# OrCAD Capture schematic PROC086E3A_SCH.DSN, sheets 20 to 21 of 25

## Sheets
20 24. FPD LINK-III DESERIALIZER: size C; title: FPD LINK-III De-SERIALIZER
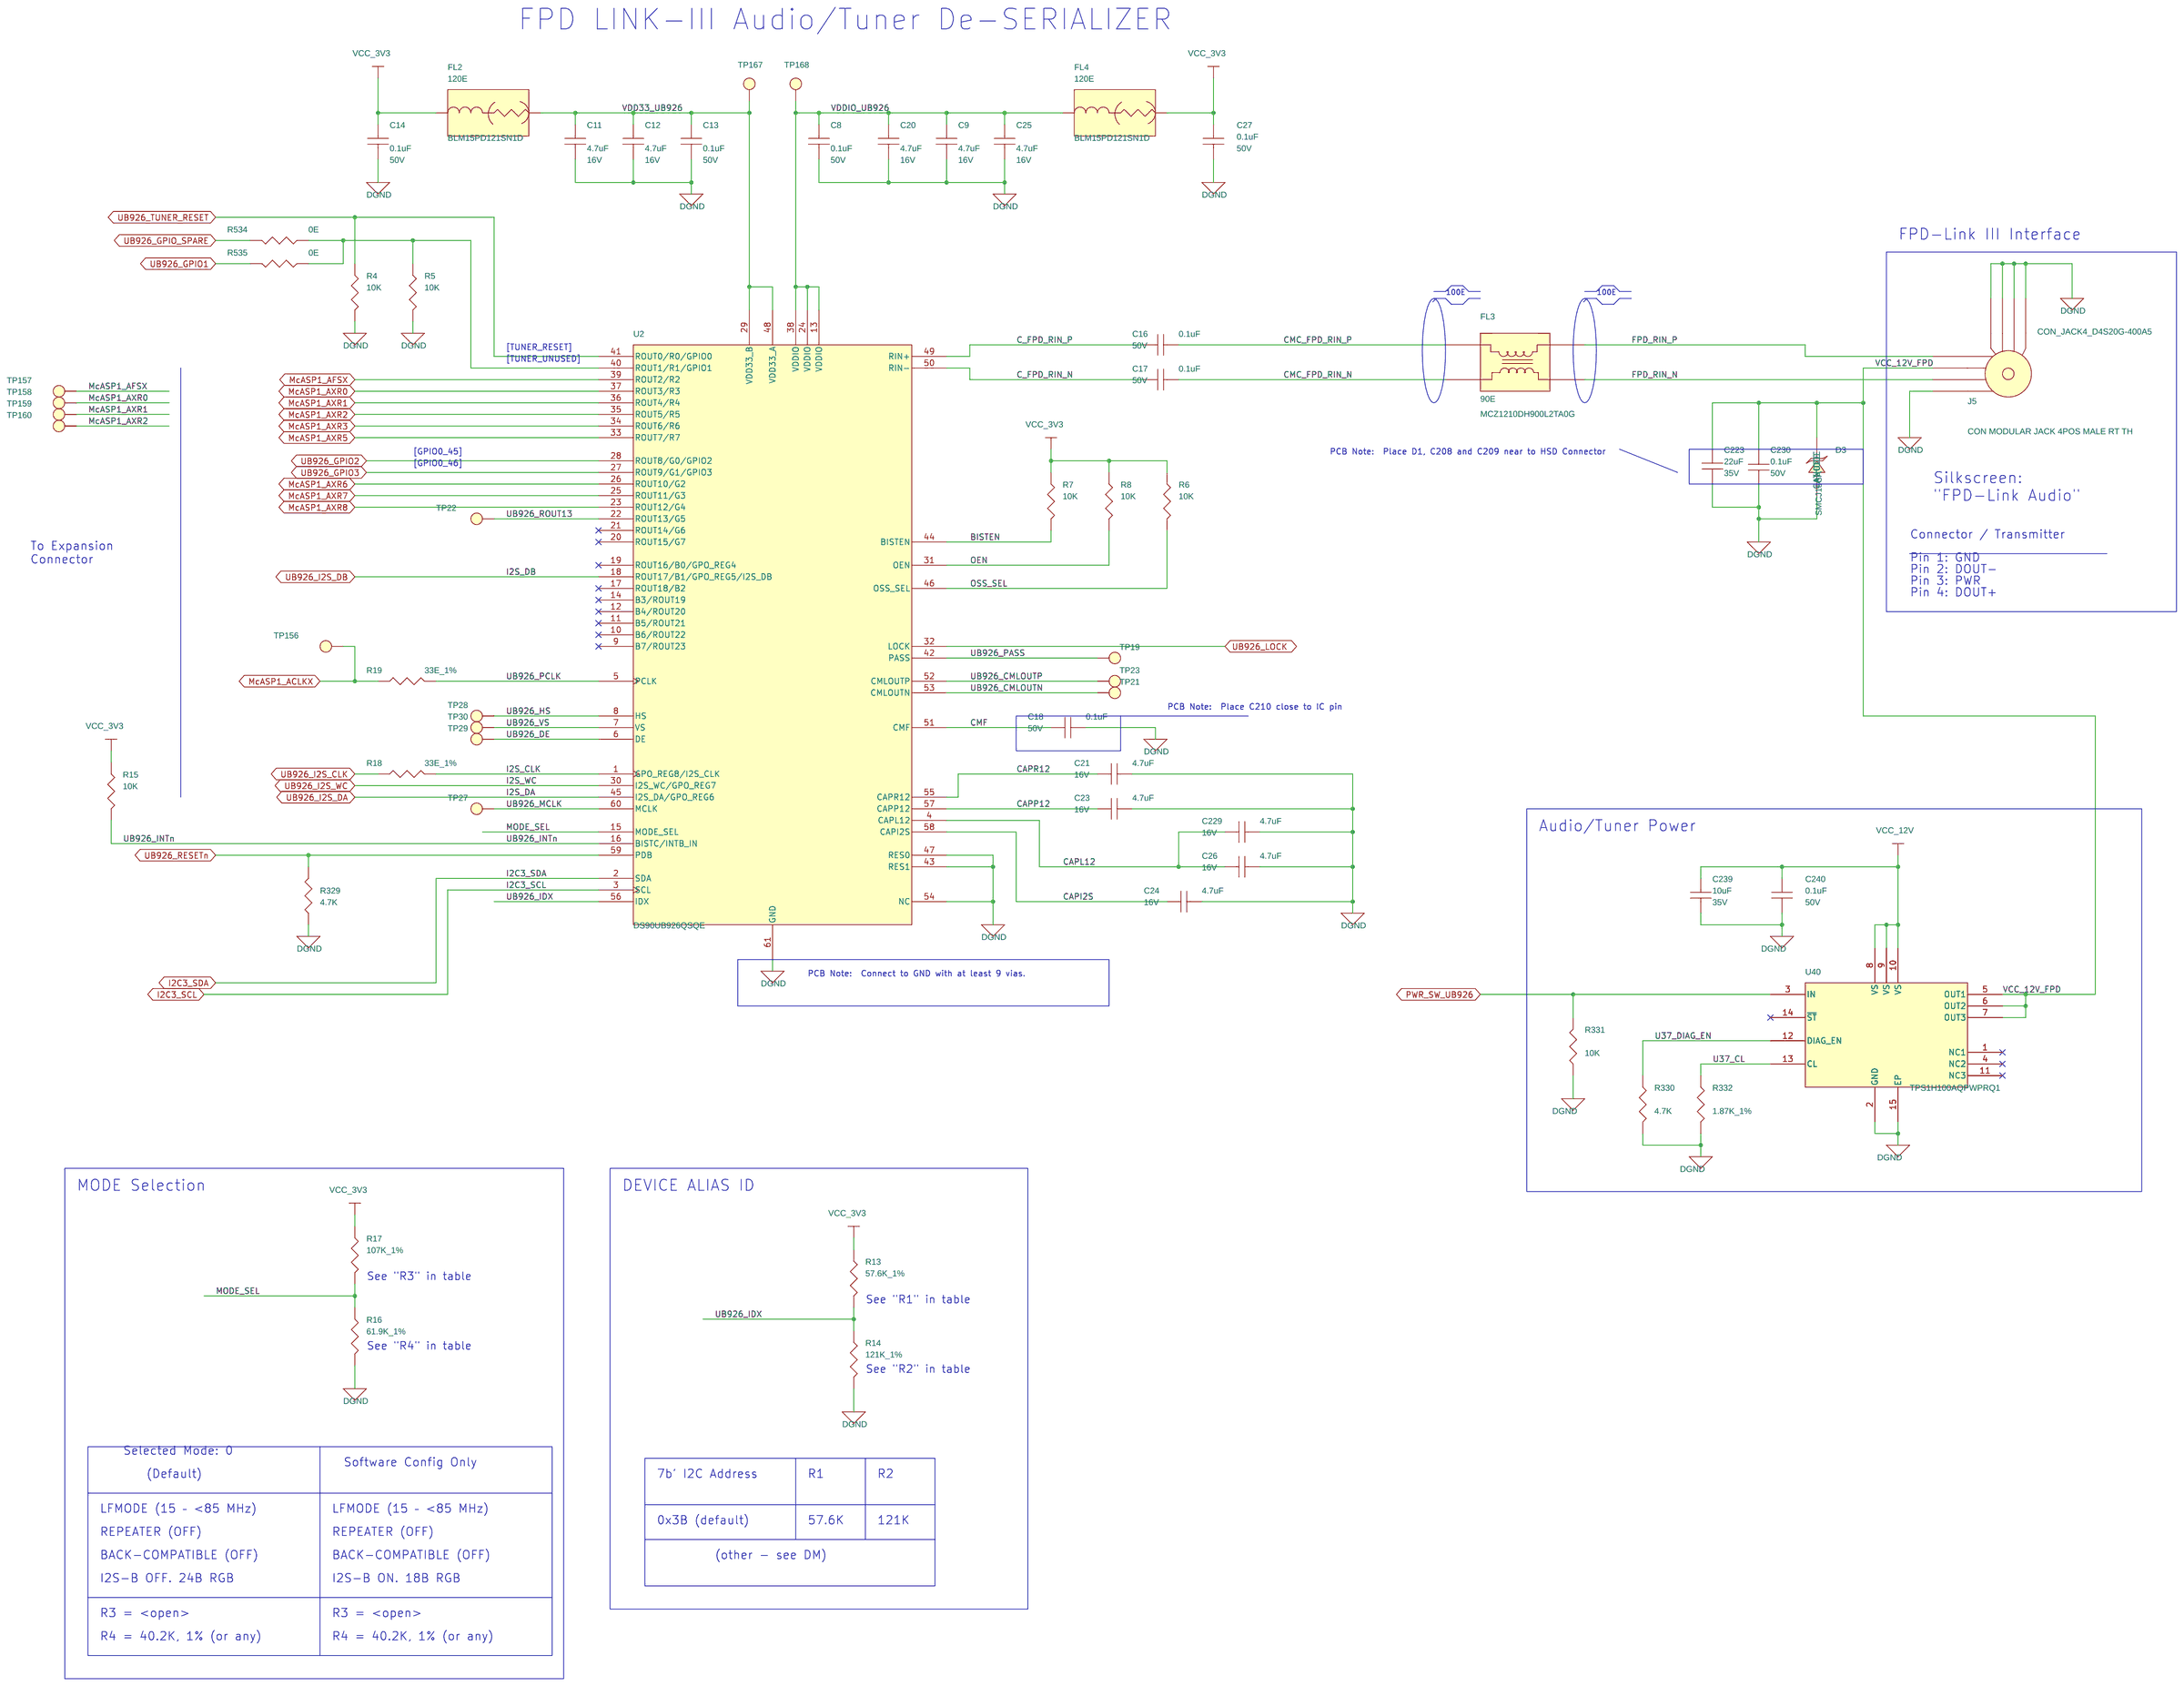
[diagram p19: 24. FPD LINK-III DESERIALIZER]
21 19. LI/OV CAM MUX: size C; title: LI/OV CAM MUX
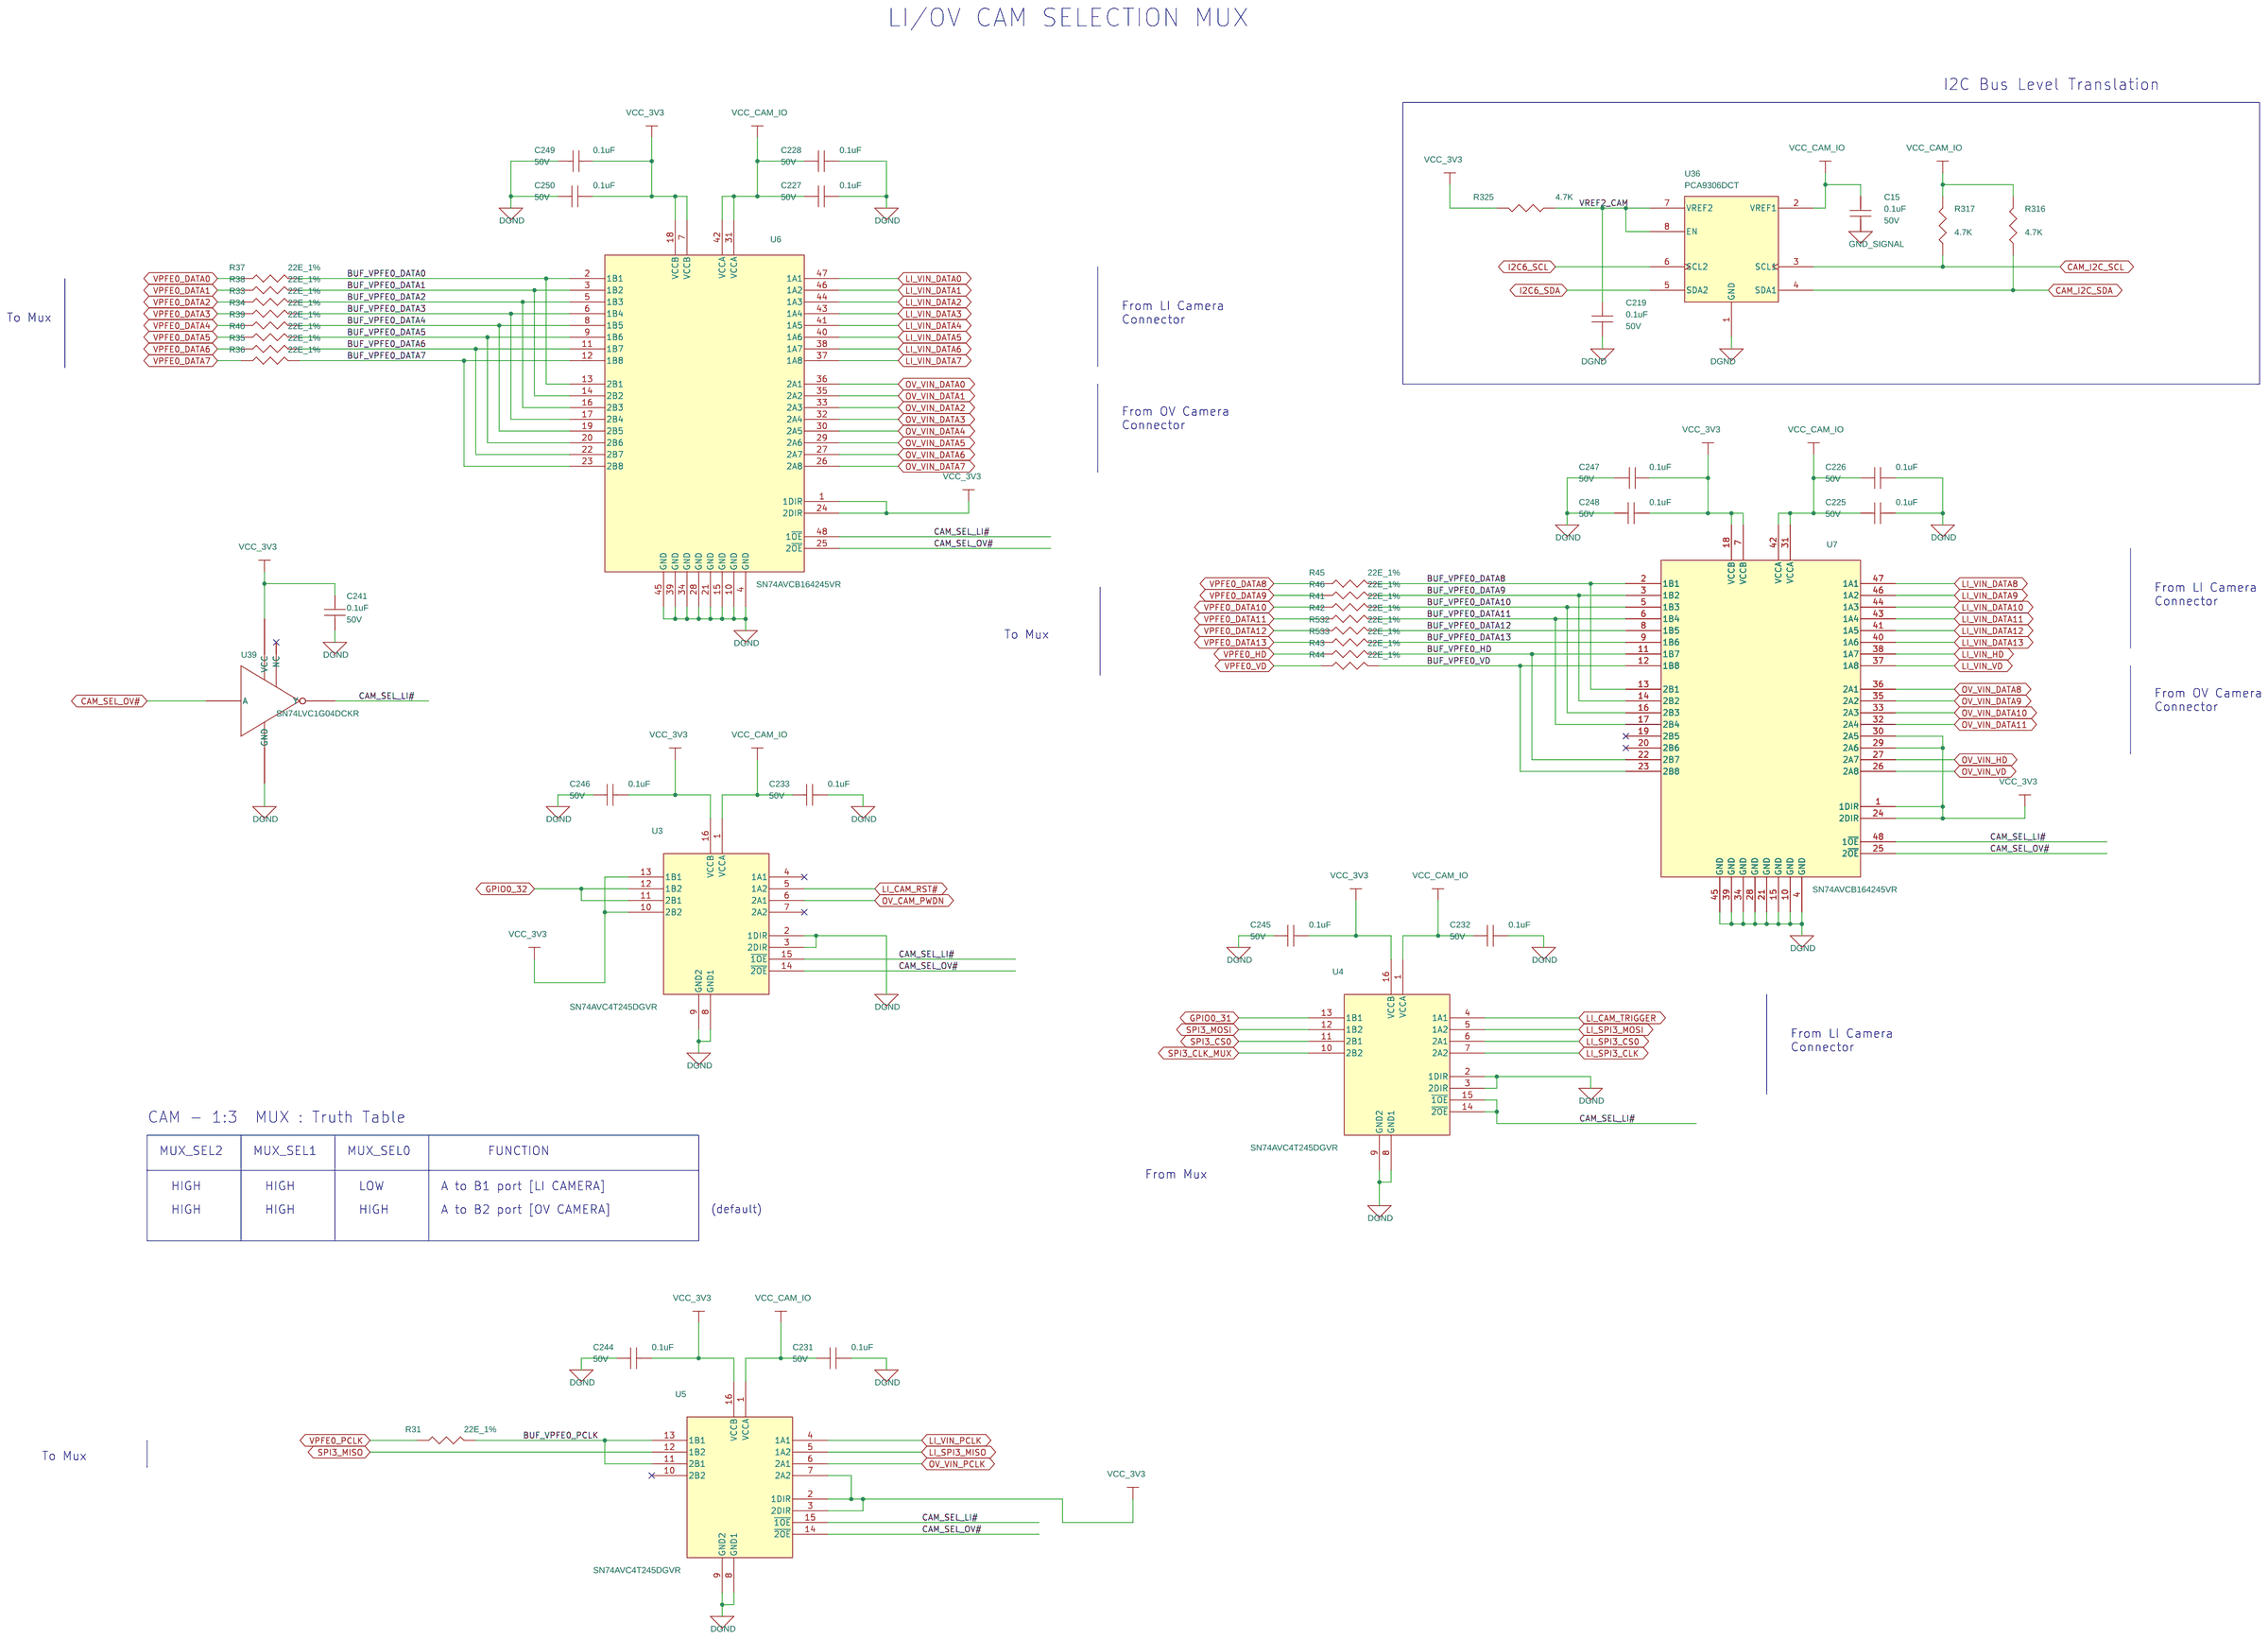
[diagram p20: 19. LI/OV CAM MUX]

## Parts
sheet 19. LI/OV CAM MUX
C15  0.1uF  [CAP0402_0-75]
C219  0.1uF  [CAP0402_0-75]
C225  0.1uF  [CAP0402_0-75]
C226  0.1uF  [CAP0402_0-75]
C227  0.1uF  [CAP0402_0-75]
C228  0.1uF  [CAP0402_0-75]
C231  0.1uF  [CAP0402_0-75]
C232  0.1uF  [CAP0402_0-75]
C233  0.1uF  [CAP0402_0-75]
C241  0.1uF  [CAP0402_0-75]
C244  0.1uF  [CAP0402_0-75]
C245  0.1uF  [CAP0402_0-75]
C246  0.1uF  [CAP0402_0-75]
C247  0.1uF  [CAP0402_0-75]
C248  0.1uF  [CAP0402_0-75]
C249  0.1uF  [CAP0402_0-75]
C250  0.1uF  [CAP0402_0-75]
R31  22E_1%  [RES0402_0-5]
R33  22E_1%  [RES0402_0-5]
R34  22E_1%  [RES0402_0-5]
R35  22E_1%  [RES0402_0-5]
R36  22E_1%  [RES0402_0-5]
R37  22E_1%  [RES0402_0-5]
R38  22E_1%  [RES0402_0-5]
R39  22E_1%  [RES0402_0-5]
R40  22E_1%  [RES0402_0-5]
R41  22E_1%  [RES0402_0-5]
R42  22E_1%  [RES0402_0-5]
R43  22E_1%  [RES0402_0-5]
R44  22E_1%  [RES0402_0-5]
R45  22E_1%  [RES0402_0-5]
R46  22E_1%  [RES0402_0-5]
R316  4.7K  [RES0402_0-5]
R317  4.7K  [RES0402_0-5]
R325  4.7K  [RES0402_0-5]
R532  22E_1%  [RES0402_0-5]
R533  22E_1%  [RES0402_0-5]
U3  SN74AVC4T245DGVR  [TVSOP16_15-74_150X180]
U4  SN74AVC4T245DGVR  [TVSOP16_15-74_150X180]
U5  SN74AVC4T245DGVR  [TVSOP16_15-74_150X180]
U6  SN74AVCB164245VR  [TVSOP48_15-74_390X180_1-2]
U7  SN74AVCB164245VR  [TVSOP48_15-74_390X180_1-2]
U36  PCA9306DCT  [SSOP8_25-59_120X110]
U39  SN74LVC1G04DCKR  [SC70-5]
sheet 24. FPD LINK-III DESERIALIZER
C8  0.1uF  [CAP0402_0-75]
C9  4.7uF  [CAP0603_1]
C11  4.7uF  [CAP0603_1]
C12  4.7uF  [CAP0603_1]
C13  0.1uF  [CAP0402_0-75]
C14  0.1uF  [CAP0402_0-75]
C16  0.1uF  [CAP0402_0-75]
C17  0.1uF  [CAP0402_0-75]
C18  0.1uF  [CAP0402_0-75]
C20  4.7uF  [CAP0603_1]
C21  4.7uF  [CAP0603_1]
C23  4.7uF  [CAP0603_1]
C24  4.7uF  [CAP0603_1]
C25  4.7uF  [CAP0603_1]
C26  4.7uF  [CAP0603_1]
C27  0.1uF  [CAP0402_0-75]
C223  22uF  [CAP1206_2]
C229  4.7uF  [CAP0603_1]
C230  0.1uF  [CAP0402_0-75]
C239  10uF  [CAP1206_2]
C240  0.1uF  [CAP0402_0-75]
D3  SMCJ15CA  [DIO_SMC]
FL2  120E  [EMIFIL_BLM15A_0402_0-6]
FL3  90E  [FILT4_MCZ1210DH_60X50_SMD_0-6]
FL4  120E  [EMIFIL_BLM15A_0402_0-6]
J5  CON_JACK4_D4S20G-400A5  [CON_JACK4_D4S20G-400A5_P_R_T_10-6]
R4  10K  [RES0402_0-5]
R5  10K  [RES0402_0-5]
R6  10K  [RES0402_0-5]
R7  10K  [RES0402_0-5]
R8  10K  [RES0402_0-5]
R13  57.6K_1%  [RES0402_0-5]
R14  121K_1%  [RES0402_0-5]
R15  10K  [RES0402_0-5]
R16  61.9K_1%  [RES0402_0-5]
R17  107K_1%  [RES0402_0-5]
R18  33E_1%  [RES0402_0-5]
R19  33E_1%  [RES0402_0-5]
R329  4.7K  [RES0402_0-5]
R330  4.7K  [RES0402_0-5]
R331  10K  [RES0402_0-5]
R332  1.87K_1%  [RES0402_0-5]
R534  0E  [RES0402_0-5]
R535  0E  [RES0402_0-5]
TP19  TP40_SMD  [TP40_SMD]
TP21  TP40_SMD  [TP40_SMD]
TP22  TP40_SMD  [TP40_SMD]
TP23  TP40_SMD  [TP40_SMD]
TP27  TP40_SMD  [TP40_SMD]
TP28  TP40_SMD  [TP40_SMD]
TP29  TP40_SMD  [TP40_SMD]
TP30  TP40_SMD  [TP40_SMD]
TP156  TP20_SMD  [TP20_SMD]
TP157  TP20_SMD  [TP20_SMD]
TP158  TP20_SMD  [TP20_SMD]
TP159  TP20_SMD  [TP20_SMD]
TP160  TP20_SMD  [TP20_SMD]
TP167  TP40_SMD  [TP40_SMD]
TP168  TP40_SMD  [TP40_SMD]
U2  DS90UB926QSQE  [WQFN60_19-68_360X360_0-8]
U40  TPS1H100AQPWPRQ1  [HTSSOP14_TPS1H100-Q1_180X200_1-2]

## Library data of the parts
C8 C13-C18 C27 C219 C225-C228 C230-C233 C240 C241 C244-C250 = CAP: CAP CERAMIC 0.1uF 50V 10% X7R 0402; Chkd/date: VASANTHA/281216; Crtd /date: CHAITHANYA/051011; Custom_Duty: 15%; Customs_HS_Code: 85322990; Distributor_name: DIGIKEY; Distributor_part_number: 445-173610-1-ND; Footprint Path: Y:\MIS_DATABASE\Library\ALTIUM_TOOL\PCB_FOOTPRINTS\Altium_Footprint_Lib.PcbLib; Height: 0.60MM; Library Path: Y:\MIS_DATABASE\Library\ALTIUM_TOOL\SCHEMATICS_PARTS\MS_DISCRETE_Library.schlib; Mfr_name: TDK CORPORATION; Mfr_part_number: C1005X7R1H104K050BE; Mistral Part No: 120011100014-R; Package: 0402; Part_type: CAPACITORS\CERAMIC; Project: VP-4000-BASE-BOARD; RoHS: RoHS; Temperature: -55°C+125°C; Tolerance: 10%; Voltage: 50V; Wattage: NA; Weight: 0.65mg; Datasheet: Y:\MIS_DATABASE\DATASHEETS\CAPACITORS\TDK_C-SER_FEB19.PDF
R31 R33-R46 R532 R533 = RESISTOR: RES 22E 1/16W 1% 0402; Chkd/date: SUHAS/290910; Crtd /date: MAZHAR/090909; Cust_part_number: 4700-80047E; Custom_Duty: 15%; Customs_HS_Code: 85332119; Distributor_name: DIGIKEY; Distributor_part_number: 311-22.0LRCT-ND; Footprint Path: Y:\MIS_DATABASE\Library\ALTIUM_TOOL\PCB_FOOTPRINTS\Altium_Footprint_Lib.PcbLib; Height: 0.40MM; Library Path: Y:\MIS_DATABASE\Library\ALTIUM_TOOL\SCHEMATICS_PARTS\MS_DISCRETE_Library.schlib; Mfr_name: YAGEO AMERICA; Mfr_part_number: RC0402FR-0722RL; Mistral Part No: 110009090004-R; Package: 0402; Part_type: RESISTORS\FIXED; Project: VMEFMCD; RoHS: RoHS; Temperature: -55°C+155°C; Tolerance: 1%; Voltage: NA; Wattage: 1/16W; Weight: 0.65mg; Datasheet: Y:\MIS_DATABASE\DATASHEETS\RESISTORS\RCXXXXL-SER_MAR18.PDF
R316 R317 R325 R329 R330 = RESISTOR: RES 4.7K 1/16W 5% 0402; Chkd/date: VASANTHA/281216; Crtd /date: BAVISH/010611; Custom_Duty: 15%; Customs_HS_Code: 85332119; Distributor_name: DIGIKEY; Distributor_part_number: 541-4.7KJCT-ND; Footprint Path: Y:\MIS_DATABASE\Library\ALTIUM_TOOL\PCB_FOOTPRINTS\Altium_Footprint_Lib.PcbLib; Height: 0.40MM; Library Path: Y:\MIS_DATABASE\Library\ALTIUM_TOOL\SCHEMATICS_PARTS\MS_DISCRETE_Library.schlib; Mfr_name: VISHAY; Mfr_part_number: CRCW04024K70JNED; Mistral Part No: 110011060001-R; Package: 0402; Part_type: RESISTORS\FIXED; Project: AM4515_EVM_LCD; RoHS: RoHS; Temperature: -55°C+155°C; Tolerance: 5%; Voltage: NA; Wattage: 1/16W; Weight: 0.65mg; Datasheet: Y:\MIS_DATABASE\DATASHEETS\RESISTORS\CRCW0603.PDF
U3-U5 = SN74AVC4T245DGVR_TVSOP16: IC 4-BIT DUAL SUPPLY BUS TRANSCEIVER TVSOP16; Chkd/date: SUHAS/251010; Crtd /date: MAZHAR/201109; Custom_Duty: 15%; Customs_HS_Code: 85423100; Distributor_name: DIGIKEY; Distributor_part_number: 296-18054-1-ND; Height: 1.20MM; Mfr_name: TEXAS INSTRUMENTS; Mistral Part No: 141009110005-P; Package: TVSOP16; Part_type: ICS\DIGITAL\COMBINATIONAL; Project: GOLDEN-I; RoHS: Sb/ Br FREE; Temperature: -40°C+85°C; Datasheet: Y:\MIS_DATABASE\DATASHEETS\ICS\DIGITAL\BUSTRANSCEIVER\SN74AVC4T245.PDF
U6 U7 = SN74AVCB164245VR_TVSOP48: IC 16-BIT DUAL-SUPPLY BUS TRANSCEIVER WITH 3-STATE O/Ps TVSOP48; Chkd/date: SUHAS/031110; Crtd /date: USMAN/300808; Custom_Duty: 15%; Customs_HS_Code: 85423100; Distributor_name: DIGIKEY; Distributor_part_number: 296-15550-1-ND; Footprint Path: Y:\MIS_DATABASE\Library\ALTIUM_TOOL\PCB_FOOTPRINTS\Altium_Footprint_Lib.PcbLib; Height: 1.20MM; Library Path: Y:\MIS_DATABASE\Library\ALTIUM_TOOL\SCHEMATICS_PARTS\MS_TELECOM_Library.schlib; Mfr_name: TEXAS INSTRUMENTS; Mistral Part No: 143009030062-R; Package: TVSOP48; Part_type: ICS\TELECOM\TRANSCEIVER; Project: MDC; Remarks: TBD Schematics symbol missing in database; RoHS: RoHS; Temperature: -40°C+85°C; Tolerance: NA; Voltage: NA; Wattage: NA; Weight: 123.5mg; Datasheet: Y:\MIS_DATABASE\DATASHEETS\ICS\DIGITAL\BUSTRANSCEIVER\SN74AVCB1642.PDF
U36 = PCA9306DCT_SSOP8: IC VOLTAGE LEVEL TRANSLATORS SSOP8; Chkd/date: MAZHAR/231210; Crtd /date: BAVISH/221210; Custom_Duty: 15%; Customs_HS_Code: 85423100; Distributor_name: DIGIKEY; Distributor_part_number: 296-18509-1-ND; Height: 1.30MM; Mfr_name: TEXAS INSTRUMENTS; Mfr_part_number: PCA9306DCTR; Mistral Part No: 141010120015-R; Package: SSOP8; Part_type: ICS\INTERFACE; Project: CENTAURUS; RoHS: RoHS; Temperature: -40°C+85°C; Tolerance: NA; Voltage: NA; Wattage: NA; Weight: NA; Datasheet: Y:\MIS_DATABASE\DATASHEETS\ICS\INTERFACE\PCA9306DCT.PDF
U39 = SN74LVC1G04DCKR_SC70-5: IC SINGLE INVERTER GATE SC70-5; Chkd/date: SUHAS/221010; Crtd /date: USMAN/150709; Custom_Duty: 15%; Customs_HS_Code: 85423100; Distributor_name: DIGIKEY; Distributor_part_number: 296-11600-1-ND; Height: 1.10MM; Mfr_name: TEXAS INSTRUMENTS; Mistral Part No: 141009070007-R; Part_type: ICS\DIGITAL\GATES; Project: BUG_BASE-II; RoHS: Sb/ Br FREE; Temperature: -40°C+85°C; Datasheet: Y:\MIS_DATABASE\DATASHEETS\ICS\DIGITAL\GATES\SN74LVC1G04-1.PDF
C9 C11 C12 C20 C21 C23-C26 C229 = CAP: CAP CERAMIC 4.7uF 16V 10% X6S 0603; Chkd/date: MANIRAJA/050618; Crtd /date: ALVY/050618; Custom_Duty: 15%; Customs_HS_Code: 85322990; Distributor_name: DIGIKEY; Distributor_part_number: 445-9118-1-ND; Footprint Path: Y:\MIS_DATABASE\Library\ALTIUM_TOOL\PCB_FOOTPRINTS\Altium_Footprint_Lib.PcbLib; Height: 1.00MM; Library Path: Y:\MIS_DATABASE\Library\ALTIUM_TOOL\SCHEMATICS_PARTS\MS_DISCRETE_Library.schlib; Mfr_name: TDK CORPORATION; Mfr_part_number: C1608X6S1C475K080AC; Mistral Part No: 120018060012-R; Package: 0603; Part_type: CAPACITORS\CERAMIC; Project: NPOL_RDAQ_ONBOARD-RX; RoHS: RoHS; Temperature: -55°C+105°C; Tolerance: 10%; Voltage: 16V; Wattage: NA; Weight: 2mg; Datasheet: Y:\MIS_DATABASE\DATASHEETS\CAPACITORS\TDK_C-SER-JUL17.PDF
C223 = CAP: CAP CERAMIC 22uF 35V 20% X5R 1206; Chkd/date: MANIRAJA/130318; Crtd /date: MANIRAJA/130318; Custom_Duty: 15%; Customs_HS_Code: 85322990; Distributor_name: DIGIKEY; Distributor_part_number: 445-8045-1-ND; Footprint Path: Y:\MIS_DATABASE\Library\ALTIUM_TOOL\PCB_FOOTPRINTS\Altium_Footprint_Lib.PcbLib; Height: 1.80MM; Library Path: Y:\MIS_DATABASE\Library\ALTIUM_TOOL\SCHEMATICS_PARTS\MS_DISCRETE_Library.schlib; Mfr_name: TDK CORPORATION; Mfr_part_number: C3216X5R1V226M160AC; Mistral Part No: 120018030003-R; Package: 1206; Part_type: CAPACITORS\CERAMIC; Project: TI_SVB_MAXWELL_VPS; RoHS: RoHS; Temperature: -55°C+85°C; Tolerance: 20%; Voltage: 35V; Wattage: NA; Weight: 16.2mg; Datasheet: Y:\MIS_DATABASE\DATASHEETS\CAPACITORS\C3216X5R1V226M160AC.PDF
C239 = CAP: CAP CERAMIC 10uF 35V 10% X5R 1206; Chkd/date: MANIRAJA/160519; Crtd /date: ALVY/160519; Custom_Duty: 15%; Customs_HS_Code: 85322990; Distributor_name: DIGIKEY; Distributor_part_number: 587-2484-1-ND; Footprint Path: Y:\MIS_DATABASE\Library\ALTIUM_TOOL\PCB_FOOTPRINTS\Altium_Footprint_Lib.PcbLib; Height: 1.80MM; Library Path: Y:\MIS_DATABASE\Library\ALTIUM_TOOL\SCHEMATICS_PARTS\MS_DISCRETE_Library.schlib; Mfr_name: TAIYO YUDEN; Mfr_part_number: GMK316BJ106KL-T; Mistral Part No: 120019050012-R; Package: 1206; Part_type: CAPACITORS\CERAMIC; Project: J7ES_SOM_DUAL-LEO_PMIC; RoHS: RoHS; Temperature: -55°C+85°C; Tolerance: 10%; Voltage: 35V; Wattage: NA; Weight: 16.2mg; Datasheet: Y:\MIS_DATABASE\DATASHEETS\CAPACITORS\TY-EMKXXX-2019.PDF
D3 = DIODE_TVS: DIODE TVS 1500W 15V SMC; Chkd/date: SUHAS/061010; Crtd /date: MAZHAR/011007; Custom_Duty: 15%; Customs_HS_Code: 85412900; Distributor_name: DIGIKEY; Distributor_part_number: SMCJ15CALFCT-ND; Height: 2.62MM; Mfr_name: LITTLE FUSE; Mistral Part No: 130009030286-R; Package: SMC; Part_type: DIODE\TVS; Project: TELEMETRY ENCODER; RoHS: RoHS; Temperature: -55°C+150°C; Voltage: 15V; Wattage: 1500W; Weight: 0.21g; Datasheet: Y:\MIS_DATABASE\DATASHEETS\DISCRETES\DIODES\SMCJ-LITT.PDF
FL2 FL4 = EMIFILTER_IND: IND FERRITE BEAD CHIP 120E 1.3A 0402; Chkd/date: VASANTHA/010117; Crtd /date: CHAITHANYA/150312; Custom_Duty: 24%; Customs_HS_Code: 85437099; Distributor_name: DIGIKEY; Distributor_part_number: 490-5203-1-ND; Footprint Path: Y:\MIS_DATABASE\Library\ALTIUM_TOOL\PCB_FOOTPRINTS\Altium_Footprint_Lib.PcbLib; Height: 0.55MM; Library Path: Y:\MIS_DATABASE\Library\ALTIUM_TOOL\SCHEMATICS_PARTS\MS_FILTER_Library.schlib; Mfr_name: MURATA; Mfr_part_number: BLM15PD121SN1D; Mistral Part No: 130012030043-R; Package: 0402; Part_type: FILTER; Project: GEN_3-8; RoHS: RoHS; Temperature: -55°C+125°C; Tolerance: 25%; Voltage: NA; Wattage: NA; Weight: 0.65mg; Datasheet: Y:\MIS_DATABASE\DATASHEETS\DISCRETES\INDUCTORS\BLM15X-SER.PDF
FL3 = EMIFILTER_ACM: FILTER COMMON MODE 90E 100mA SMD; Chkd/date: MANIRAJA/220818; Crtd /date: ALVY/220818; Custom_Duty: 24%; Customs_HS_Code: 85437099; Distributor_name: DIGIKEY; Distributor_part_number: 445-174550-1-ND; Footprint Path: Y:\MIS_DATABASE\Library\ALTIUM_TOOL\PCB_FOOTPRINTS\Altium_Footprint_Lib.PcbLib; Height: 0.60MM; Library Path: Y:\MIS_DATABASE\Library\ALTIUM_TOOL\SCHEMATICS_PARTS\MS_FILTER_Library.schlib; Mfr_name: TDK CORPORATION; Mfr_part_number: MCZ1210DH900L2TA0G; Mistral Part No: 130018080027-R; Package: SMD; Part_type: FILTER; Project: TI_J7ES_EVM_FUSION2_SER_CAP; RoHS: RoHS; Temperature: -40°C+85°C; Tolerance: 25%; Voltage: NA; Wattage: NA; Weight: 3mg; Datasheet: Y:\MIS_DATABASE\DATASHEETS\ICS\MISC\MCZ1210DH-SER.PDF
J5 = CON_JACK4_EXG.0B.304: CON MODULAR JACK 4POS MALE RT TH; Chkd/date: MANIRAJA/031018; Crtd /date: ALVY/070818; Custom_Duty: 24%; Customs_HS_Code: 85369090; Distributor_name: DIGIKEY; Distributor_part_number: 1868-1516-1-ND; Footprint Path: Y:\MIS_DATABASE\Library\ALTIUM_TOOL\PCB_FOOTPRINTS\Altium_Footprint_Lib.PcbLib; Height: 10.60MM; Library Path: Y:\MIS_DATABASE\Library\ALTIUM_TOOL\SCHEMATICS_PARTS\MS_CONNECTOR_Library.schlib; Mfr_name: ROSENBERGER; Mfr_part_number: D4S20G-400A5-C; Mistral Part No: 150018080004-R; Package: THRU-HOLE; Part_type: CONNECTOR\JACK; Project: TI_J7ES_EVM_IB; RoHS: RoHS; Temperature: -40°C+105°C; Tolerance: NA; Voltage: NA; Wattage: NA; Weight: 8.6g; Datasheet: Y:\MIS_DATABASE\DATASHEETS\CONNECTORS\D4S20G-400A5-Y.PDF
R4-R6 R8 R15 R331 = RESISTOR: RES 10K 1/16W 5% 0402; Chkd/date: VASANTHA/061216; Crtd /date: MAZHAR/230805; Custom_Duty: 15%; Customs_HS_Code: 85332119; Distributor_name: DIGIKEY; Distributor_part_number: 311-10KJRCT-ND; Footprint Path: Y:\MIS_DATABASE\Library\ALTIUM_TOOL\PCB_FOOTPRINTS\Altium_Footprint_Lib.PcbLib; Height: 0.40MM; Library Path: Y:\MIS_DATABASE\Library\ALTIUM_TOOL\SCHEMATICS_PARTS\MS_DISCRETE_Library.schlib; Mfr_name: YAGEO AMERICA; Mfr_part_number: RC0402JR-0710KL; Mistral Part No: 110011060021-R; Package: 0402; Part_type: RESISTORS\FIXED; Project: HSE; RoHS: RoHS; Temperature: -55°C+155°C; Tolerance: 5%; Voltage: NA; Wattage: 1/16W; Weight: 0.65mg; Datasheet: Y:\MIS_DATABASE\DATASHEETS\RESISTORS\RCXXXXL-SER_MAR18.PDF
R7 = RESISTOR: RES 10K 1/16W 5% 0402; Assembly_Instruction: DNI; Chkd/date: VASANTHA/061216; Crtd /date: MAZHAR/230805; Custom_Duty: 15%; Customs_HS_Code: 85332119; Distributor_name: DIGIKEY; Distributor_part_number: 311-10KJRCT-ND; Footprint Path: Y:\MIS_DATABASE\Library\ALTIUM_TOOL\PCB_FOOTPRINTS\Altium_Footprint_Lib.PcbLib; Height: 0.40MM; Library Path: Y:\MIS_DATABASE\Library\ALTIUM_TOOL\SCHEMATICS_PARTS\MS_DISCRETE_Library.schlib; Mfr_name: YAGEO AMERICA; Mfr_part_number: RC0402JR-0710KL; Mistral Part No: 110011060021-R; Package: 0402; Part_type: RESISTORS\FIXED; Project: HSE; RoHS: RoHS; Temperature: -55°C+155°C; Tolerance: 5%; Voltage: NA; Wattage: 1/16W; Weight: 0.65mg; Datasheet: Y:\MIS_DATABASE\DATASHEETS\RESISTORS\RCXXXXL-SER_MAR18.PDF
R13 = RESISTOR: RES 57.6K 1/16W 1% 0402; Chkd/date: USMAN/021214; Crtd /date: VASANTHA/101114; Custom_Duty: 15%; Customs_HS_Code: 85332119; Distributor_name: DIGIKEY; Distributor_part_number: 541-57.6KLCT-ND; Footprint Path: Y:\MIS_DATABASE\Library\ALTIUM_TOOL\PCB_FOOTPRINTS\Altium_Footprint_Lib.PcbLib; Height: 0.40MM; Library Path: Y:\MIS_DATABASE\Library\ALTIUM_TOOL\SCHEMATICS_PARTS\MS_DISCRETE_Library.schlib; Mfr_name: VISHAY; Mfr_part_number: CRCW040257K6FKED; Mistral Part No: 110014110002-R; Package: 0402; Part_type: RESISTORS\FIXED; Project: GALILEO_EVM; RoHS: RoHS; Temperature: -55°C+155°C; Tolerance: 1%; Voltage: NA; Wattage: 1/16W; Weight: 0.65mg; Datasheet: Y:\MIS_DATABASE\DATASHEETS\RESISTORS\CRCW0603.PDF
R14 = RESISTOR: RES 121K 1/10W 1% 0402; Chkd/date: MANIRAJA/150319; Crtd /date: MANIRAJA/150319; Custom_Duty: 15%; Customs_HS_Code: 85332119; Distributor_name: DIGIKEY; Distributor_part_number: P121KLCT-ND; Footprint Path: Y:\MIS_DATABASE\Library\ALTIUM_TOOL\PCB_FOOTPRINTS\Altium_Footprint_Lib.PcbLib; Height: 0.40MM; Library Path: Y:\MIS_DATABASE\Library\ALTIUM_TOOL\SCHEMATICS_PARTS\MS_DISCRETE_Library.schlib; Mfr_name: PANASONIC-ECG; Mfr_part_number: ERJ-2RKF1213X; Mistral Part No: 110019040110-R; Package: 0402; Part_type: RESISTORS\FIXED; Project: G4SLIM; RoHS: RoHS; Temperature: -55°C+155°C; Tolerance: 1%; Voltage: NA; Wattage: 1/10W; Weight: 0.8mg; Datasheet: Y:\MIS_DATABASE\DATASHEETS\RESISTORS\PAN-ERJSER_NOV17.PDF
R16 = RESISTOR: RES 61.9K 1/16W 1% 0402; Chkd/date: MAZHAR/280508; Crtd /date: USMAN/190508; Custom_Duty: 15%; Customs_HS_Code: 85332119; Distributor_name: DIGIKEY; Distributor_part_number: 311-61.9KLRCT-ND; Footprint Path: Y:\MIS_DATABASE\Library\ALTIUM_TOOL\PCB_FOOTPRINTS\Altium_Footprint_Lib.PcbLib; Height: 0.40MM; Library Path: Y:\MIS_DATABASE\Library\ALTIUM_TOOL\SCHEMATICS_PARTS\MS_DISCRETE_Library.schlib; Mfr_name: YAGEO AMERICA; Mfr_part_number: RC0402FR-0761K9L; Mistral Part No: 110009031042-R; Package: 0402; Part_type: RESISTORS\FIXED; Project: KMB; RoHS: RoHS; Temperature: -55°C+155°C; Tolerance: 1%; Voltage: NA; Wattage: 1/16W; Weight: 0.65mg; Datasheet: Y:\MIS_DATABASE\DATASHEETS\RESISTORS\RCXXXXL-SER_MAR18.PDF
R17 = RESISTOR: RES 107K 1/10W 1% 0402; Assembly_Instruction: DNI; Chkd/date: RAVI/081110; Crtd /date: BAVISH/051010; Custom_Duty: 15%; Customs_HS_Code: 85332119; Distributor_name: DIGIKEY; Distributor_part_number: P107KLCT-ND; Footprint Path: Y:\MIS_DATABASE\Library\ALTIUM_TOOL\PCB_FOOTPRINTS\Altium_Footprint_Lib.PcbLib; Height: 0.40MM; Library Path: Y:\MIS_DATABASE\Library\ALTIUM_TOOL\SCHEMATICS_PARTS\MS_DISCRETE_Library.schlib; Mfr_name: PANASONIC-ECG; Mfr_part_number: ERJ-2RKF1073X; Mistral Part No: 110010100002-R; Package: 0402; Part_type: RESISTORS\FIXED; Project: ITS; RoHS: RoHS; Temperature: -55°C+155°C; Tolerance: 1%; Voltage: NA; Wattage: 1/10W; Weight: 0.8mg; Datasheet: Y:\MIS_DATABASE\DATASHEETS\RESISTORS\PAN-ERJSER_NOV17.PDF
R18 R19 = RESISTOR: RES 33E 1/10W 1% 0402; Chkd/date: VASANTHA/061216; Crtd /date: JEBRAN/171114; Custom_Duty: 15%; Customs_HS_Code: 85332119; Distributor_name: DIGIKEY; Distributor_part_number: P33.0LCT-ND; Footprint Path: Y:\MIS_DATABASE\Library\ALTIUM_TOOL\PCB_FOOTPRINTS\Altium_Footprint_Lib.PcbLib; Height: 0.40MM; Library Path: Y:\MIS_DATABASE\Library\ALTIUM_TOOL\SCHEMATICS_PARTS\MS_DISCRETE_Library.schlib; Mfr_name: PANASONIC-ECG; Mfr_part_number: ERJ-2RKF33R0X; Mistral Part No: 110014110006-R; Package: 0402; Part_type: RESISTORS\FIXED; Project: ZK BIOMETRIC; RoHS: RoHS; Temperature: -55°C+155°C; Tolerance: 1%; Voltage: NA; Wattage: 1/10W; Weight: 0.8mg; Datasheet: Y:\MIS_DATABASE\DATASHEETS\RESISTORS\PAN-ERJSER_NOV17.PDF
R332 = RESISTOR: RES 1.87K 1/10W 1% 0402; Chkd/date: MAZHAR/151208; Crtd /date: USMAN/251108; Custom_Duty: 15%; Customs_HS_Code: 85332119; Distributor_name: DIGIKEY; Distributor_part_number: P1.87KLCT-ND; Footprint Path: Y:\MIS_DATABASE\Library\ALTIUM_TOOL\PCB_FOOTPRINTS\Altium_Footprint_Lib.PcbLib; Height: 0.40MM; Library Path: Y:\MIS_DATABASE\Library\ALTIUM_TOOL\SCHEMATICS_PARTS\MS_DISCRETE_Library.schlib; Mfr_name: PANASONIC-ECG; Mfr_part_number: ERJ-2RKF1871X; Mistral Part No: 110009030145-R; Package: 0402; Part_type: RESISTORS\FIXED; Project: KHAN_HSST; RoHS: RoHS; Temperature: -55°C+155°C; Tolerance: 1%; Voltage: NA; Wattage: 1/10W; Weight: 0.8mg; Datasheet: Y:\MIS_DATABASE\DATASHEETS\RESISTORS\PAN-ERJSER_NOV17.PDF
R534 = RESISTOR: RES 0E 1/10W JUMPER 0402; Assembly_Instruction: DNI; Chkd/date: VASANTHA/061216; Crtd /date: NAVEED/201014; Custom_Duty: 15%; Customs_HS_Code: 85332119; Distributor_name: DIGIKEY; Distributor_part_number: P0.0JCT-ND; Footprint Path: Y:\MIS_DATABASE\Library\ALTIUM_TOOL\PCB_FOOTPRINTS\Altium_Footprint_Lib.PcbLib; Height: 0.40MM; IBISSP_MODLES: VALUE REPEATING 2 TIME; Library Path: Y:\MIS_DATABASE\Library\ALTIUM_TOOL\SCHEMATICS_PARTS\MS_DISCRETE_Library.schlib; Mfr_name: PANASONIC-ECG; Mfr_part_number: ERJ-2GE0R00X; Mistral Part No: 110018030052-R; Package: 0402; Part_type: RESISTORS\FIXED; Project: AEGIS POM; RoHS: RoHS; Temperature: -55°C+155°C; Tolerance: NA; Voltage: NA; Wattage: 1/10W; Weight: 0.8mg; Datasheet: Y:\MIS_DATABASE\DATASHEETS\RESISTORS\PAN-ERJSER_NOV17.PDF
R535 = RESISTOR: RES 0E 1/10W JUMPER 0402; Chkd/date: VASANTHA/061216; Crtd /date: NAVEED/201014; Custom_Duty: 15%; Customs_HS_Code: 85332119; Distributor_name: DIGIKEY; Distributor_part_number: P0.0JCT-ND; Footprint Path: Y:\MIS_DATABASE\Library\ALTIUM_TOOL\PCB_FOOTPRINTS\Altium_Footprint_Lib.PcbLib; Height: 0.40MM; IBISSP_MODLES: VALUE REPEATING 2 TIME; Library Path: Y:\MIS_DATABASE\Library\ALTIUM_TOOL\SCHEMATICS_PARTS\MS_DISCRETE_Library.schlib; Mfr_name: PANASONIC-ECG; Mfr_part_number: ERJ-2GE0R00X; Mistral Part No: 110018030052-R; Package: 0402; Part_type: RESISTORS\FIXED; Project: AEGIS POM; RoHS: RoHS; Temperature: -55°C+155°C; Tolerance: NA; Voltage: NA; Wattage: 1/10W; Weight: 0.8mg; Datasheet: Y:\MIS_DATABASE\DATASHEETS\RESISTORS\PAN-ERJSER_NOV17.PDF
TP19 TP21-TP23 TP27-TP30 TP167 TP168 = TESTPOINT: TESTPOINT CIR 40 SMD; Chkd/date: MAZHAR/190505; Crtd /date: MAZHAR/190505; Distributor_name: NA; Distributor_part_number: NA; Footprint Path: Y:\MIS_DATABASE\Library\ALTIUM_TOOL\PCB_FOOTPRINTS\Altium_Footprint_Lib.PcbLib; Height: NA; Library Path: Y:\MIS_DATABASE\Library\ALTIUM_TOOL\SCHEMATICS_PARTS\MS_DISCRETE_Library.schlib; MECHANICAL 3D STEP FILE: NA; Mfr_name: LOCAL; Mistral Part No: 130009030933; Package: SMD; Project: RAINIER-3; RoHS: NA; Temperature: NA; Tolerance: NA; Voltage: NA; Wattage: NA; Weight: NA; Datasheet: NA
TP156-TP160 = TESTPOINT: TESTPOINT CIR 20 SMD; Chkd/date: SHREESHAIL/171006; Crtd /date: MAZHAR/171006; Custom_Duty: NA; Customs_HS_Code: NA; Distributor_name: NA; Distributor_part_number: NA; Footprint Path: Y:\MIS_DATABASE\Library\ALTIUM_TOOL\PCB_FOOTPRINTS\Altium_Footprint_Lib.PcbLib; Height: NA; Library Path: Y:\MIS_DATABASE\Library\ALTIUM_TOOL\SCHEMATICS_PARTS\MS_DISCRETE_Library.schlib; MECHANICAL 3D STEP FILE: NA; Mfr_name: LOCAL; Mistral Part No: NA; Package: SMD; Project: BT MODULE_CSRBC04; RoHS: NA; Temperature: NA; Tolerance: NA; Voltage: NA; Wattage: NA; Weight: NA; Datasheet: NA
U2 = DS90UB926QSQ_WQFN60_TI: IC 5-85MHz 24BIT COLOR FPD-LINK III DESERIALIZER WITH BI-DIR CONTROL CH WQFN60; Chkd/date: MANIRAJA/180718; Crtd /date: ALVY/180718; Custom_Duty: 15%; Customs_HS_Code: 85423100; Distributor_name: DIGIKEY; Distributor_part_number: 296-38938-1-ND; Footprint Path: Y:\MIS_DATABASE\Library\ALTIUM_TOOL\PCB_FOOTPRINTS\Altium_Footprint_Lib.PcbLib; Height: 0.80MM; Library Path: Y:\MIS_DATABASE\Library\ALTIUM_TOOL\SCHEMATICS_PARTS\MS_MISCINTERFACE_Library.schlib; Library Ref: DS90UB926QSQ_WQFN60; Mfr_name: TEXAS INSTRUMENTS; Mfr_part_number: DS90UB926QSQE/NOPB; Mistral Part No: 141018070005-R; Package: WQFN60; Part_type: ICS\INTERFACE; Project: TI_J7ES_EVM_IB; RoHS: RoHS; Temperature: -40°C+105°C; Tolerance: NA; Voltage: NA; Wattage: NA; Weight: 220.8mg; Datasheet: Y:\MIS_DATABASE\DATASHEETS\ICS\INTERFACE\DS90UB926Q-Q1.PDF
U40 = TPS1H100A-Q1_HTSSOP14: IC 40V 100mE 1-CHANNEL SMART HIGH-SIDE POWER SWITCH HTSSOP14; Chkd/date: MANIRAJA/140818; Crtd /date: ALVY/140818; Custom_Duty: 15%; Customs_HS_Code: 85423100; Distributor_name: DIGIKEY; Distributor_part_number: 296-42052-1-ND; Footprint Path: Y:\MIS_DATABASE\Library\ALTIUM_TOOL\PCB_FOOTPRINTS\Altium_Footprint_Lib.PcbLib; Height: 1.20MM; Library Path: Y:\MIS_DATABASE\Library\ALTIUM_TOOL\SCHEMATICS_PARTS\MS_MISCPOWER_Library.schlib; Mfr_name: TEXAS INSTRUMENTS; Mistral Part No: 142018080008-R; Package: HTSSOP14; Part_type: ICS\POWER; Project: TI_J7ES_EVM_FUSION2_SER_CAP; RoHS: RoHS; Temperature: -40°C+125°C; Tolerance: NA; Voltage: NA; Wattage: NA; Weight: 58mg; Datasheet: Y:\MIS_DATABASE\DATASHEETS\ICS\POWER\TPS1H100-Q1.PDF

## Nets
DGND: C8.2 C9.2 C11.2 C12.2 C13.2 C14.2 C15.2 C18.2 C20.2 C21.2 C23.2 C24.2 C25.2 C26.2 C27.2 C219.2 C223.2 C225.2 C226.2 C227.2 C228.2 C229.2 C230.1 C231.2 C232.2 C233.2 C239.2 C240.2 C241.2 C244.1 C245.1 C246.1 C247.2 C248.1 C249.2 C250.1 D3.2(ANODE) J5.1 J5.SH1 J5.SH2 J5.SH3 J5.SH4 R4.1 R5.1 R14.2 R16.2 R329.2 R330.2 R331.2 R332.2 U2.43(RES1) U2.47(RES0) U2.54(NC) U2.61(GND) U3.2(1DIR) U3.3(2DIR) U3.8(GND1) U3.9(GND2) U4.2(1DIR) U4.3(2DIR) U4.8(GND1) U4.9(GND2) U5.8(GND1) U5.9(GND2) U6.4(GND) U6.10(GND) U6.15(GND) U6.21(GND) U6.28(GND) U6.34(GND) U6.39(GND) U6.45(GND) U7.4(GND) U7.10(GND) U7.15(GND) U7.21(GND) U7.28(GND) U7.34(GND) U7.39(GND) U7.45(GND) U36.1(GND) U39.3(GND) U40.2(GND) U40.15(EP) ; also on sheet 5 6 7 8 9 10 11 12 13 14 15 16 17 18 19 22 23 25
VCC_3V3: C14.1 C27.1 C241.1 C244.2 C245.2 C246.2 C247.1 C248.2 C249.1 C250.2 FL2.1 FL4.2 R6.2 R7.2 R8.2 R13.1 R15.2 R17.1 R325.1 U3.10(2B2) U3.13(1B1) U3.16(VCCB) U4.16(VCCB) U5.2(1DIR) U5.3(2DIR) U5.7(2A2) U5.16(VCCB) U6.1(1DIR) U6.7(VCCB) U6.18(VCCB) U6.24(2DIR) U7.1(1DIR) U7.7(VCCB) U7.18(VCCB) U7.24(2DIR) U7.29(2A6) U7.30(2A5) U39.5(VCC) ; also on sheet 5 14 15 16 17 18 19 22 23 25
VCC_12V: C239.1 C240.1 U40.8(VS) U40.9(VS) U40.10(VS) ; also on sheet 5 16 18
VCC_12V_FPD: C223.1 C230.2 D3.1(CATHODE) J5.3 U40.5(OUT1) U40.6(OUT2) U40.7(OUT3)
VCC_CAM_IO: C15.1 C225.1 C226.1 C227.1 C228.1 C231.1 C232.1 C233.1 R316.1 R317.1 U3.1(VCCA) U4.1(VCCA) U5.1(VCCA) U6.31(VCCA) U6.42(VCCA) U7.31(VCCA) U7.42(VCCA) U36.2(VREF1) ; also on sheet 17
VDD33_UB926: C11.1 C12.1 C13.1 FL2.2 TP167.1(TP) U2.29(VDD33_B) U2.48(VDD33_A)
VDDIO_UB926: C8.1 C9.1 C20.1 C25.1 FL4.1 TP168.1(TP) U2.13(VDDIO) U2.24(VDDIO) U2.38(VDDIO)
BISTEN: R7.1 U2.44(BISTEN)
BUF_VPFE0_DATA0: R37.2 U6.2(1B1) U6.13(2B1)
BUF_VPFE0_DATA1: R38.2 U6.3(1B2) U6.14(2B2)
BUF_VPFE0_DATA2: R33.2 U6.5(1B3) U6.16(2B3)
BUF_VPFE0_DATA3: R34.2 U6.6(1B4) U6.17(2B4)
BUF_VPFE0_DATA4: R39.2 U6.8(1B5) U6.19(2B5)
BUF_VPFE0_DATA5: R40.2 U6.9(1B6) U6.20(2B6)
BUF_VPFE0_DATA6: R35.2 U6.11(1B7) U6.22(2B7)
BUF_VPFE0_DATA7: R36.2 U6.12(1B8) U6.23(2B8)
BUF_VPFE0_DATA8: R45.2 U7.2(1B1) U7.13(2B1)
BUF_VPFE0_DATA9: R46.2 U7.3(1B2) U7.14(2B2)
BUF_VPFE0_DATA10: R41.2 U7.5(1B3) U7.16(2B3)
BUF_VPFE0_DATA11: R42.2 U7.6(1B4) U7.17(2B4)
BUF_VPFE0_DATA12: R532.2 U7.8(1B5)
BUF_VPFE0_DATA13: R533.2 U7.9(1B6)
BUF_VPFE0_HD: R43.2 U7.11(1B7) U7.22(2B7)
BUF_VPFE0_PCLK: R31.2 U5.11(2B1) U5.13(1B1)
BUF_VPFE0_VD: R44.2 U7.12(1B8) U7.23(2B8)
C_FPD_RIN_N: C17.1 U2.50(RIN-)
C_FPD_RIN_P: C16.1 U2.49(RIN+)
CAM_I2C_SCL: R317.2 U36.3(SCL1) ; also on sheet 17
CAM_I2C_SDA: R316.2 U36.4(SDA1) ; also on sheet 17
CAM_SEL_LI#: U3.15(~{1OE}) U4.14(~{2OE}) U4.15(~{1OE}) U5.15(~{1OE}) U6.48(1~{OE}) U7.48(1~{OE}) U39.4(Y)
CAM_SEL_OV#: U3.14(~{2OE}) U5.14(~{2OE}) U6.25(2~{OE}) U7.25(2~{OE}) U39.2(A) ; also on sheet 5
CAPI2S: C24.1 U2.58(CAPI2S)
CAPL12: C26.1 C229.1 U2.4(CAPL12)
CAPP12: C23.1 U2.57(CAPP12)
CAPR12: C21.1 U2.55(CAPR12)
CMC_FPD_RIN_N: C17.2 FL3.1
CMC_FPD_RIN_P: C16.2 FL3.2
CMF: C18.1 U2.51(CMF)
FPD_RIN_N: FL3.4 J5.2
FPD_RIN_P: FL3.3 J5.4
GPIO0_31: U4.13(1B1) ; also on sheet 14
GPIO0_32: U3.11(2B1) U3.12(1B2) ; also on sheet 14
I2C3_SCL: U2.3(SCL) ; also on sheet 5 18 22 23
I2C3_SDA: U2.2(SDA) ; also on sheet 5 18 22 23
I2C6_SCL: U36.6(SCL2) ; also on sheet 5
I2C6_SDA: U36.5(SDA2) ; also on sheet 5
I2S_CLK: R18.2 U2.1(GPO_REG8/I2S_CLK)
LI_CAM_RST#: U3.5(1A2) ; also on sheet 17
LI_CAM_TRIGGER: U4.4(1A1) ; also on sheet 17
LI_SPI3_CLK: U4.7(2A2) ; also on sheet 17
LI_SPI3_CS0: U4.6(2A1) ; also on sheet 17
LI_SPI3_MISO: U5.5(1A2) ; also on sheet 17
LI_SPI3_MOSI: U4.5(1A2) ; also on sheet 17
LI_VIN_DATA0: U6.47(1A1) ; also on sheet 17
LI_VIN_DATA1: U6.46(1A2) ; also on sheet 17
LI_VIN_DATA2: U6.44(1A3) ; also on sheet 17
LI_VIN_DATA3: U6.43(1A4) ; also on sheet 17
LI_VIN_DATA4: U6.41(1A5) ; also on sheet 17
LI_VIN_DATA5: U6.40(1A6) ; also on sheet 17
LI_VIN_DATA6: U6.38(1A7) ; also on sheet 17
LI_VIN_DATA7: U6.37(1A8) ; also on sheet 17
LI_VIN_DATA8: U7.47(1A1) ; also on sheet 17
LI_VIN_DATA9: U7.46(1A2) ; also on sheet 17
LI_VIN_DATA10: U7.44(1A3) ; also on sheet 17
LI_VIN_DATA11: U7.43(1A4) ; also on sheet 17
LI_VIN_DATA12: U7.41(1A5) ; also on sheet 17
LI_VIN_DATA13: U7.40(1A6) ; also on sheet 17
LI_VIN_HD: U7.38(1A7) ; also on sheet 17
LI_VIN_PCLK: U5.4(1A1) ; also on sheet 17
LI_VIN_VD: U7.37(1A8) ; also on sheet 17
McASP1_ACLKX: R19.1 TP156.1(TP) ; also on sheet 5
McASP1_AFSX: TP157.1(TP) U2.39(ROUT2/R2) ; also on sheet 5
McASP1_AXR0: TP158.1(TP) U2.37(ROUT3/R3) ; also on sheet 5
McASP1_AXR1: TP159.1(TP) U2.36(ROUT4/R4) ; also on sheet 5
McASP1_AXR2: TP160.1(TP) U2.35(ROUT5/R5) ; also on sheet 5
McASP1_AXR3: U2.34(ROUT6/R6) ; also on sheet 5
McASP1_AXR5: U2.33(ROUT7/R7) ; also on sheet 5
McASP1_AXR6: U2.26(ROUT10/G2) ; also on sheet 5
McASP1_AXR7: U2.25(ROUT11/G3) ; also on sheet 5
McASP1_AXR8: U2.23(ROUT12/G4) ; also on sheet 5
MODE_SEL: R16.1 R17.2 U2.15(MODE_SEL)
OEN: R8.1 U2.31(OEN)
OSS_SEL: R6.1 U2.46(OSS_SEL)
OV_CAM_PWDN: U3.6(2A1) ; also on sheet 17
OV_VIN_DATA0: U6.36(2A1) ; also on sheet 17
OV_VIN_DATA1: U6.35(2A2) ; also on sheet 17
OV_VIN_DATA2: U6.33(2A3) ; also on sheet 17
OV_VIN_DATA3: U6.32(2A4) ; also on sheet 17
OV_VIN_DATA4: U6.30(2A5) ; also on sheet 17
OV_VIN_DATA5: U6.29(2A6) ; also on sheet 17
OV_VIN_DATA6: U6.27(2A7) ; also on sheet 17
OV_VIN_DATA7: U6.26(2A8) ; also on sheet 17
OV_VIN_DATA8: U7.36(2A1) ; also on sheet 17
OV_VIN_DATA9: U7.35(2A2) ; also on sheet 17
OV_VIN_DATA10: U7.33(2A3) ; also on sheet 17
OV_VIN_DATA11: U7.32(2A4) ; also on sheet 17
OV_VIN_HD: U7.27(2A7) ; also on sheet 17
OV_VIN_PCLK: U5.6(2A1) ; also on sheet 17
OV_VIN_VD: U7.26(2A8) ; also on sheet 17
PWR_SW_UB926: R331.1 U40.3(IN) ; also on sheet 5
SPI3_CLK_MUX: U4.10(2B2) ; also on sheet 14
SPI3_CS0: U4.11(2B1) ; also on sheet 5
SPI3_MISO: U5.12(1B2) ; also on sheet 14
SPI3_MOSI: U4.12(1B2) ; also on sheet 14
U37_CL: R332.1 U40.13(CL)
U37_DIAG_EN: R330.1 U40.12(DIAG_EN)
UB926_CMLOUTN: TP21.1(TP) U2.53(CMLOUTN)
UB926_CMLOUTP: TP23.1(TP) U2.52(CMLOUTP)
UB926_DE: TP29.1(TP) U2.6(DE)
UB926_GPIO1: R535.1 ; also on sheet 5
UB926_GPIO2: U2.28(ROUT8/G0/GPIO2) ; also on sheet 5
UB926_GPIO3: U2.27(ROUT9/G1/GPIO3) ; also on sheet 5
UB926_GPIO_SPARE: R534.1 ; also on sheet 5
UB926_HS: TP28.1(TP) U2.8(HS)
UB926_I2S_CLK: R18.1 ; also on sheet 14
UB926_I2S_DA: U2.45(I2S_DA/GPO_REG6) ; also on sheet 14
UB926_I2S_DB: U2.18(ROUT17/B1/GPO_REG5/I2S_DB) ; also on sheet 14
UB926_I2S_WC: U2.30(I2S_WC/GPO_REG7) ; also on sheet 14
UB926_IDX: R13.2 R14.1 U2.56(IDX)
UB926_INTn: R15.1 U2.16(BISTC/INTB_IN)
UB926_LOCK: U2.32(LOCK) ; also on sheet 5
UB926_MCLK: TP27.1(TP) U2.60(MCLK)
UB926_PASS: TP19.1(TP) U2.42(PASS)
UB926_PCLK: R19.2 U2.5(PCLK)
UB926_RESETn: R329.1 U2.59(PDB) ; also on sheet 5
UB926_ROUT13: TP22.1(TP) U2.22(ROUT13/G5)
UB926_TUNER_RESET: R4.2 U2.41(ROUT0/R0/GPIO0) ; also on sheet 5
UB926_VS: TP30.1(TP) U2.7(VS)
VPFE0_DATA0: R37.1 ; also on sheet 14
VPFE0_DATA1: R38.1 ; also on sheet 14
VPFE0_DATA2: R33.1 ; also on sheet 14
VPFE0_DATA3: R34.1 ; also on sheet 14
VPFE0_DATA4: R39.1 ; also on sheet 14
VPFE0_DATA5: R40.1 ; also on sheet 14
VPFE0_DATA6: R35.1 ; also on sheet 14
VPFE0_DATA7: R36.1 ; also on sheet 14
VPFE0_DATA8: R45.1 ; also on sheet 14
VPFE0_DATA9: R46.1 ; also on sheet 14
VPFE0_DATA10: R41.1 ; also on sheet 14
VPFE0_DATA11: R42.1 ; also on sheet 14
VPFE0_DATA12: R532.1 ; also on sheet 14
VPFE0_DATA13: R533.1 ; also on sheet 14
VPFE0_HD: R43.1 ; also on sheet 14
VPFE0_PCLK: R31.1 ; also on sheet 14
VPFE0_VD: R44.1 ; also on sheet 14
VREF2_CAM: C219.1 R325.2 U36.7(VREF2) U36.8(EN)
N24589481: R5.2 R534.2 R535.2 U2.40(ROUT1/R1/GPIO1)

Not connected (* = marked no-connect by the designer): U2 9(B7/ROUT23)* 10(B6/ROUT22)* 11(B5/ROUT21)* 12(B4/ROUT20)* 14(B3/ROUT19)* 17(ROUT18/B2)* 19(ROUT16/B0/GPO_REG4)* 20(ROUT15/G7)* 21(ROUT14/G6)*; U3 4(1A1)* 7(2A2)*; U5 10(2B2)*; U7 19(2B5)* 20(2B6)*; U39 1(NC)*; U40 1(NC1)* 4(NC2)* 11(NC3)* 14(~{ST})*

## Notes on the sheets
sheet 20
- FPD LINK-III Audio/Tuner De-SERIALIZER
- FPD-Link III Interface
- 100E
- 100E
- [TUNER_RESET]
- [TUNER_UNUSED]
- [GPIO0_45]
- PCB Note:  Place D1, C208 and C209 near to HSD Connector
- [GPIO0_46]
- Silkscreen:
  "FPD-Link Audio"
- Connector / Transmitter
- To Expansion
  Connector
- Pin 1: GND
- Pin 2: DOUT-
- Pin 3: PWR
- Pin 4: DOUT+
- PCB Note:  Place C210 close to IC pin
- Audio/Tuner Power
- PCB Note:  Connect to GND with at least 9 vias.
- MODE Selection
- DEVICE ALIAS ID
- See "R3" in table
- See "R1" in table
- See "R4" in table
- See "R2" in table
- Selected Mode: 0
- Software Config Only
- (Default)
- 7b' I2C Address
- R1
- R2
- LFMODE (15 – <85 MHz)
- LFMODE (15 – <85 MHz)
- 0x3B (default)
- 57.6K
- 121K
- REPEATER (OFF)
- REPEATER (OFF)
- BACK-COMPATIBLE (OFF)
- BACK-COMPATIBLE (OFF)
- (other - see DM)
- I2S-B OFF. 24B RGB
- I2S-B ON. 18B RGB
- R3 = <open>
- R3 = <open>
- R4 = 40.2K, 1% (or any)
- R4 = 40.2K, 1% (or any)
sheet 21
- LI/OV CAM SELECTION MUX
- I2C Bus Level Translation
- From LI Camera
  Connector
- To Mux
- From OV Camera
  Connector
- From LI Camera
  Connector
- To Mux
- From OV Camera
  Connector
- From LI Camera
  Connector
- CAM - 1:3  MUX : Truth Table
- MUX_SEL2
- MUX_SEL1
- MUX_SEL0
- FUNCTION
- From Mux
- HIGH
- HIGH
- LOW
- A to B1 port [LI CAMERA]
- HIGH
- HIGH
- HIGH
- A to B2 port [OV CAMERA]
- (default)
- To Mux
